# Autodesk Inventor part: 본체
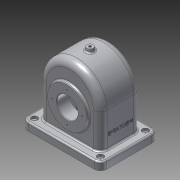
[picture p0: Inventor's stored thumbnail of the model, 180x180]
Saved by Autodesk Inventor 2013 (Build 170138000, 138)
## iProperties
Created: 2016-10
Part Number: 본체
Material: 알루미늄 6061
Document SubType Name: Modeling
Designer: Administrator
Density: 2.71 g/cm^3
Mass: 1165.05 g
Surface Area: 1200.05 cm^2
Volume: 429.908 cm^3
Author: Administrator
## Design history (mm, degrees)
sketch "스케치1"
  geometry: L1 (-58, 65)-(58, 65); L2 (58, 65)-(58, 0); L3 (58, 0)-(-58, 0); L4 (-58, 0)-(-58, 65); L5 (-58, 65)-(-58, 80); L6 (58, 65)-(58, 80); A1 r 58 centre (0, 80) between (58, 80) and (-58, 80); 2 further points
  constraints: 12 end point, 3 parallel, 2 point on circle, 1 centre point, 1 coincident, 1 collinear, 1 horizontal, 1 midpoint, 1 perpendicular, 1 vertical alignment
  dimensions: "d0" = 116 distance of L2.end L3.end; "d2" = 65 distance of L1.end L2.end; "d4" = 80 distance of point (0, 0) A1.centre; "d5" = 58 radius of A1
extrude "돌출1" new body sketch "스케치1" stored distance "d6" = 77; taper "d7" = 0 deg
sketch "스케치2"
  geometry: L1 (58, 80)-(58, 0) reference; L2 (58, 0)-(-58, 0) reference; L3 (-58, 0)-(-58, 80) reference; L4 (52, 80)-(52, -10); L5 (-52, -10)-(-52, 80); L6 (-52, -10)-(52, -10); A1 r 58 centre (0, 80) between (58, 80) and (-58, 80) reference; A2 r 52 centre (0, 80) between (52, 80) and (-52, 80); 1 further point
  constraints: 6 end point, 2 point on circle, 1 centre point, 1 parallel, 1 perpendicular, 1 other
  dimensions: "d8" = 6 distance between parallel lines of L3 L5; "d9" = 52 radius of A2; "d10" = 10 distance between parallel lines of L6 L2
extrude "돌출2" cut sketch "스케치2" stored distance "d11" = 67; taper "d12" = 0 deg
fillet "모깎기1" dims "d13" = 8
fillet "모깎기2" dims "d14" = 13
sketch "스케치5"
  geometry: L1 (132, -25.5)-(132, 25.5) reference; L2 (124, 33.5)-(0, 33.5) reference; L3 (0, 33.5)-(0, 38.5) reference; L4 (0, 38.5)-(125, 38.5) reference; L5 (138, 25.5)-(138, -25.5) reference; L6 (125, -38.5)-(0, -38.5) reference; L7 (0, -38.5)-(0, -33.5) reference; L8 (0, -33.5)-(124, -33.5) reference; L9 (104.747, 33.5)-(93, 19.5); L10 (93, 19.5)-(65, 19.5); L11 (65, 43.5)-(102.5, 43.5); L12 (102.5, 43.5)-(102.5, 38.5); L13 (65, 19.5)-(65, 33.5); L14 (65, 38.5)-(65, 43.5); A1 r 8 centre (124, -25.5) between (124, -33.5) and (132, -25.5) reference; A2 r 8 centre (124, 25.5) between (132, 25.5) and (124, 33.5) reference; A3 r 13 centre (125, 25.5) between (138, 25.5) and (125, 38.5) reference; A4 r 13 centre (125, -25.5) between (125, -38.5) and (138, -25.5) reference; 1 further point
  constraints: 12 end point, 5 perpendicular, 4 point on line, 1 collinear, 1 parallel
  dimensions: "d15" = 65 distance from line of point (0, 0) L13; "d16" = 5 distance of L11.end L12.end; "d18" = 50 deg angle of L10 L9; "d19" = 56 diameter of L9.end L13; "d20" = 75 diameter of L12 L14; "d21" = 14 distance between parallel lines of L2 L10
revolve "회전1" sketch "스케치5" stored, may be unused: angle "d22" = 90 deg
sketch "스케치6"
  geometry: L1 (132, -25.5)-(132, 25.5) reference; L2 (124, 33.5)-(104.747, 33.5) reference; L3 (104.747, 33.5)-(93, 19.5) reference; L4 (93, 19.5)-(37, 19.5) reference; L5 (37, 19.5)-(25.253, 33.5) reference; L6 (25.253, 33.5)-(0, 33.5) reference; L7 (0, 33.5)-(0, 38.5) reference; L8 (0, 38.5)-(27.5, 38.5) reference; L9 (27.5, 38.5)-(27.5, 43.5) reference; L10 (27.5, 43.5)-(102.5, 43.5) reference; L11 (102.5, 43.5)-(102.5, 38.5) reference; L12 (102.5, 38.5)-(125, 38.5) reference; L13 (138, 25.5)-(138, -25.5) reference; L14 (125, -38.5)-(0, -38.5) reference; L15 (0, -38.5)-(0, -33.5) reference; L16 (0, -33.5)-(124, -33.5) reference; L17 (96, -38.5)-(65, -38.5); L18 (65, -38.5)-(65, -48.5); L19 (65, -48.5)-(96, -48.5); L20 (96, -48.5)-(96, -38.5); A1 r 8 centre (124, -25.5) between (124, -33.5) and (132, -25.5) reference; A2 r 8 centre (124, 25.5) between (132, 25.5) and (124, 33.5) reference; A3 r 13 centre (125, 25.5) between (138, 25.5) and (125, 38.5) reference; A4 r 13 centre (125, -25.5) between (125, -38.5) and (138, -25.5) reference; 1 further point
  constraints: 8 end point, 2 parallel, 1 horizontal, 1 perpendicular, 1 point on line
  dimensions: "d23" = 10 distance of L19.end L17.start; "d25" = 65 distance from line of point (0, 0) L18; "d26" = 62 diameter of L20 L18
revolve "회전2" sketch "스케치6" stored, may be unused: angle "d27" = 90 deg
hole "구멍1" diameter "d30" = 40; stored, may be unused: countersink angle "d34" = 90 deg, drill point angle "d36" = 118 deg; dims "d31" = 6, "d32" = 4, "d33" = 2, "d35" = 127.5, "d37" = 10, "d38" = 10
sketch "스케치7"
  geometry: L1 (103, -64)-(103, -13) reference; L2 (0, 0)-(90, 0) reference; L3 (-13, -64)-(-13, -13) reference; L4 (90, -77)-(0, -77) reference; L5 (-30, -93.5)-(120, -93.5); L6 (120, -93.5)-(120, 16.5); L7 (120, 16.5)-(-30, 16.5); L8 (-30, 16.5)-(-30, -93.5); L9 (-30, -93.5)-(120, 16.5); L10 (120, -93.5)-(-30, 16.5); A1 r 13 centre (90, -64) between (90, -77) and (103, -64) reference; A2 r 13 centre (90, -13) between (103, -13) and (90, 0) reference; A3 r 13 centre (0, -13) between (0, 0) and (-13, -13) reference; A4 r 13 centre (0, -64) between (-13, -64) and (0, -77) reference; 1 further point
  constraints: 12 end point, 2 midpoint, 2 parallel, 1 horizontal, 1 perpendicular
  dimensions: "d39" = 110 distance of L5.end L6.end; "d41" = 150 distance of L5.start L5.end
extrude "돌출3" join sketch "스케치7" distance "d42" = 15; taper "d43" = 0 deg
fillet "모깎기3" dims "d44" = 12
hole "구멍2" diameter "d47" = 5; stored, may be unused: countersink angle "d51" = 90 deg, drill point angle "d53" = 118 deg; dims "d45" = 10, "d46" = 10, "d48" = 6, "d49" = 12, "d50" = 5, "d52" = 25
sketch "스케치9"
  geometry: L1 (34, -48.5)-(34, -38.5) reference; L2 (34, -38.5)-(15, -38.5) reference; L3 (15, -38.5)-(15, -55) reference; L4 (15, -55)-(0, -55) reference; L5 (0, -55)-(0, -33.5) reference; L6 (0, -33.5)-(45, -33.5) reference; L7 (45, -33.5)-(45, -48.5) reference; L8 (45, -48.5)-(34, -48.5) reference; L9 (37, 19.5)-(25.253, 33.5) reference; L10 (25.253, 33.5)-(0, 33.5) reference; L11 (0, 33.5)-(0, 55) reference; L12 (0, 55)-(15, 55) reference; L13 (15, 55)-(15, 38.5) reference; L14 (15, 38.5)-(27.5, 38.5) reference; L15 (27.5, 38.5)-(27.5, 43.5) reference; L16 (27.5, 43.5)-(45, 43.5) reference; L17 (45, 43.5)-(45, 19.5) reference; L18 (45, 19.5)-(37, 19.5) reference; L19 (132, -25.5)-(132, 25.5) reference; L20 (124, 33.5)-(104.747, 33.5) reference; L21 (104.747, 33.5)-(93, 19.5) reference; L22 (93, 19.5)-(85, 19.5) reference; L23 (85, 19.5)-(85, 43.5) reference; L24 (85, 43.5)-(102.5, 43.5) reference; L25 (102.5, 43.5)-(102.5, 38.5) reference; L26 (102.5, 38.5)-(125, 38.5) reference; L27 (138, 25.5)-(138, -25.5) reference; L28 (125, -38.5)-(96, -38.5) reference; L29 (96, -38.5)-(96, -48.5) reference; L30 (96, -48.5)-(85, -48.5) reference; L31 (85, -48.5)-(85, -33.5) reference; L32 (85, -33.5)-(124, -33.5) reference; L33 (136, 0)-(144, 0); L34 (144, 0)-(144, -6); L35 (144, -6)-(136, -7.411); L36 (136, -7.411)-(136, 0); L37 (0, 0)-(169.464, 0); A1 r 8 centre (124, -25.5) between (124, -33.5) and (132, -25.5) reference; A2 r 8 centre (124, 25.5) between (132, 25.5) and (124, 33.5) reference; A3 r 13 centre (125, 25.5) between (138, 25.5) and (125, 38.5) reference; A4 r 13 centre (125, -25.5) between (125, -38.5) and (138, -25.5) reference
  constraints: 10 end point, 2 parallel, 2 perpendicular, 1 collinear
  dimensions: "d65" = 100 deg angle of L35 L27; "d66" = 144 distance from line of L37.start L34; "d68" = 6 distance of L33.end L34.end; "d71" = 2 distance between parallel lines of L36 L27
revolve "회전3" sketch "스케치9" stored, may be unused: angle "d72" = 90 deg
hole "구멍3" diameter "d76" = 4.459; stored, may be unused: countersink angle "d80" = 90 deg, drill point angle "d82" = 118 deg; dims "d74" = 10, "d75" = 10, "d77" = 15, "d78" = 12, "d79" = 5, "d81" = 20
sketch "스케치12"
  geometry: C1 r 20 at (0, 0) reference; 2 further points
  constraints: 1 vertical alignment
  dimensions: "d83" = 29 distance of C1.centre point (0, 29)
hole "구멍4" sketch "스케치12" at (0, 29) diameter "d84" = 2.459; stored, may be unused: countersink angle "d88" = 90 deg, drill point angle "d90" = 118 deg; dims "d85" = 6, "d86" = 12, "d87" = 5, "d89" = 8
sketch "스케치13"
  geometry: C1 r 20 at (0, 0) reference; 2 further points
  constraints: 1 vertical alignment
  dimensions: "d94" = 26 distance of C1.centre point (0, 26)
hole "구멍5" sketch "스케치13" at (0, 26) diameter "d95" = 2.459; stored, may be unused: countersink angle "d99" = 90 deg, drill point angle "d101" = 118 deg; dims "d96" = 6, "d97" = 12, "d98" = 5, "d100" = 8
sketch "스케치14" dims "d0" = 116, "d2" = 65, "d4" = 80, "d5" = 58
  geometry: L1 (86, 0)-(0, 0) reference; L2 (4.5, 80)-(4.5, 15) reference; 2 further points
  constraints: 1 other
  dimensions: "d105" = 38.5 distance from line of L2 point (43, 40); "d106" = 40 distance from line of L1 point (43, 40)
feature "엠보싱1" sketch "스케치14" dims "d0" = 116, "d2" = 65, "d4" = 80, "d5" = 58, "d107" = 0.5, "d108" = 0
fillet "모깎기4" dims "d109" = 3
fillet "모깎기5" dims "d110" = 3
fillet "모깎기6" dims "d111" = 3
fillet "모깎기7" dims "d112" = 3
chamfer "모따기1" distance "d113" = 1; stored, may be unused: second distance "d114" = 2, angle "d115" = 45 deg
node "솔리드1"
pattern_linear "직사각형 패턴1" dims "d56" = 126, "d59" = 86
pattern_circular "원형 패턴1" dims angle "d92" = 360 deg
pattern_circular "원형 패턴2" dims angle "d103" = 360 deg
node "절단 모서리 투영1"
node "절단 모서리 투영4"
node "절단 모서리 투영5"
node "절단 모서리 투영6"
